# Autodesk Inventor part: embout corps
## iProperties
Shininess: 64.0
Length Units: 11269
Angle Units: 11279
Time Units: 11290
Mass Units: 11283
Length Display Precision: 3
Angle Display Precision: 2
Compacted: True
Part Number: embout corps
Document SubType Name: Modeling
Created: 2005-01
Material: Par défaut
Designer: David
Manufacturer: Standard
Standards Organization: Custom
Density: 0.0
Volumn: 0.0
Area: 0.0
PropertySet Name: Model Information
Control State: 0
Master: False
Checked Out: False
Author: David
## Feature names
1. Révolution1 [Revolution]
2. Extrusion1
3. Extrusion2
4. Extrusion3
5. Symétrie2 [Mirror]
6. Extrusion5
7. Symétrie3 [Mirror]
8. Extrusion6
9. Symétrie4 [Mirror]
10. Congé2 [Fillet]
11. Congé3 [Fillet]
